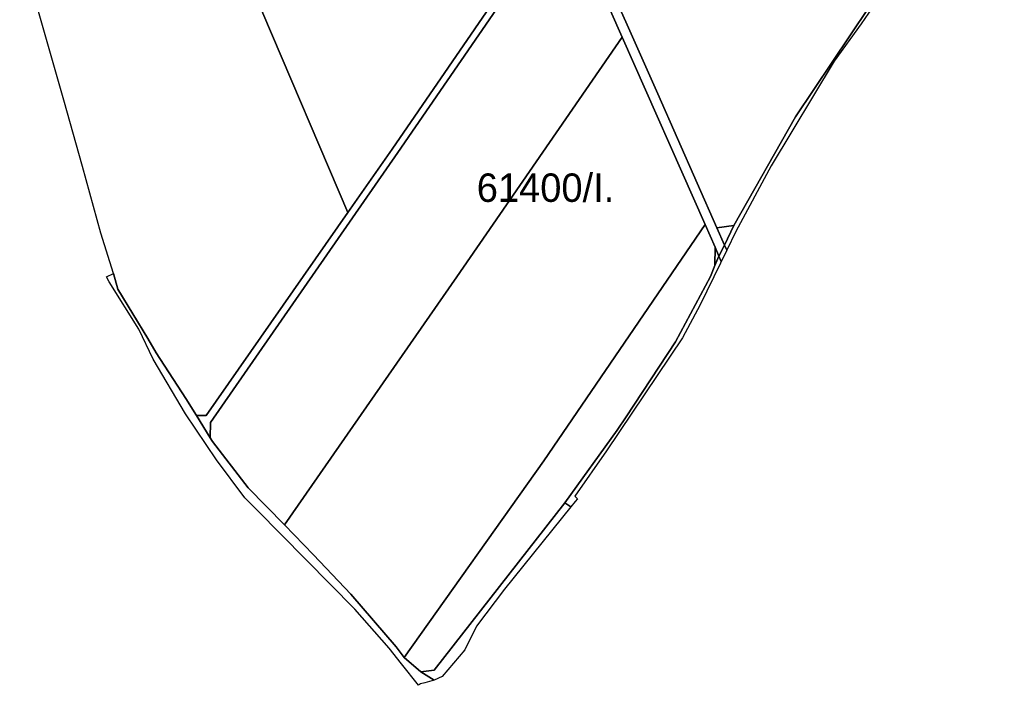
# Model space of a CAD drawing. Extents: x -522079 to -518792, y -1142400 to -1139961.
# Drawn here: x -521242 to -520720, y -1142400 to -1142050 of the extents above; entities that cross this region are included whole.
import ezdxf

# ---------------------------------------------------------------- set-up
doc = ezdxf.new("R2010")
doc.units = 0
for name, color, linetype in [('Hranice parcel', 7, 'Continuous'), ('Parcelní čísla', 7, 'Continuous'), ('Značky bodu BP', 7, 'Continuous')]:
    doc.layers.add(name, color=color, linetype=linetype)

msp = doc.modelspace()

# ---------------------------------------------------------------- linework, layer by layer
at = {"layer": 'Hranice parcel'}
for points in [[(-521009, -1141878.54), (-520995.39, -1141872.52), (-520997.93, -1141879.1), (-520967.25, -1141948.55), (-520939.85, -1142010.61), (-520905.36, -1142088.65), (-520874.16, -1142159.29), (-520870.13, -1142168.42), (-520873.11, -1142174.16), (-520875.14, -1142169.56), (-520880.4, -1142157.63), (-520924.06, -1142058.74), (-520951.97, -1141995.53), (-520958.2, -1141981.43), (-521002.46, -1141881.16)], [(-520870.13, -1142168.42), (-520868.95, -1142171.08), (-520869.86, -1142172.95), (-520871.84, -1142177.03), (-520873.11, -1142174.16)], [(-521030.26, -1142393.33), (-521023.14, -1142397.72), (-521028.09, -1142399.07), (-521030.42, -1142399.7), (-521031.51, -1142400.38), (-521040.41, -1142389.14), (-521046.98, -1142380.85), (-521064.97, -1142360.36), (-521116.76, -1142308), (-521123.05, -1142301.63), (-521137.94, -1142281.57), (-521154.24, -1142257.34), (-521171.39, -1142228.49), (-521178.89, -1142212.77), (-521194.57, -1142187.85), (-521195.91, -1142185.2), (-521192.34, -1142183.35), (-521189.97, -1142191.57), (-521174.19, -1142217.64), (-521169.79, -1142225.11), (-521154.1, -1142249.25), (-521148.58, -1142258.19), (-521141.26, -1142270.03), (-521140.11, -1142271.9), (-521121.26, -1142296.3), (-521102.18, -1142315.9), (-521086.87, -1142331.63), (-521067.07, -1142352.38), (-521043.28, -1142380.16), (-521039.1, -1142385.71)]]:
    msp.add_lwpolyline(points, close=True, dxfattribs=at)
at = {"layer": 'Parcelní čísla'}
for points in [[(-520997.93, -1141879.1), (-520995.39, -1141872.52), (-520888.63, -1141825.55), (-520837.29, -1141940.33), (-520792.44, -1142040.74), (-520794.02, -1142043.2), (-520832.63, -1142100.89), (-520865.14, -1142158.06), (-520874.16, -1142159.29), (-520905.36, -1142088.65), (-520939.85, -1142010.61), (-520967.25, -1141948.55)], [(-521068.69, -1142151.23), (-521113.51, -1142046.12), (-521154.29, -1141950.51), (-521103.17, -1141919.44), (-521009, -1141878.54), (-521002.46, -1141881.16), (-520958.2, -1141981.43), (-520958.22, -1141990.78), (-521045.32, -1142117.79)], [(-521235.48, -1141993.03), (-521178.81, -1141962.98), (-521154.29, -1141950.51), (-521113.51, -1142046.12), (-521068.69, -1142151.23), (-521143.48, -1142258.25), (-521148.58, -1142258.19), (-521154.1, -1142249.25), (-521169.79, -1142225.11), (-521174.19, -1142217.64), (-521189.97, -1142191.57), (-521192.34, -1142183.35), (-521198.94, -1142162.11), (-521208.63, -1142126.99), (-521218.49, -1142092.03), (-521226.84, -1142062.52), (-521233.47, -1142038.91), (-521241.65, -1142009.35)], [(-520865.14, -1142158.06), (-520832.63, -1142100.89), (-520794.02, -1142043.2), (-520792.44, -1142040.74), (-520762.92, -1142002.26), (-520751.6, -1141988.95), (-520732.26, -1141966.77), (-520721.33, -1141955.66), (-520719.53, -1141957.2), (-520728.5, -1141965.87), (-520748.85, -1141987.64), (-520778.35, -1142023.99), (-520792.36, -1142043.35), (-520798.04, -1142051.82), (-520812.28, -1142071.49), (-520845.48, -1142126.69), (-520864.2, -1142161.29), (-520868.95, -1142171.08), (-520870.13, -1142168.42)], [(-520951.97, -1141995.53), (-520956.88, -1141995.37), (-521042.42, -1142119.65), (-521141.2, -1142261.95), (-521141.26, -1142270.03), (-521148.58, -1142258.19), (-521143.48, -1142258.25), (-521068.69, -1142151.23), (-521045.32, -1142117.79), (-520958.22, -1141990.78), (-520958.2, -1141981.43)], [(-521011.25, -1142185.11), (-521102.18, -1142315.9), (-521121.26, -1142296.3), (-521140.11, -1142271.9), (-521141.26, -1142270.03), (-521141.2, -1142261.95), (-521042.42, -1142119.65), (-520956.88, -1141995.37), (-520951.97, -1141995.53), (-520924.06, -1142058.74)], [(-521039.1, -1142385.71), (-521043.28, -1142380.16), (-521067.07, -1142352.38), (-521086.87, -1142331.63), (-521102.18, -1142315.9), (-521011.25, -1142185.11), (-520924.06, -1142058.74), (-520880.4, -1142157.63), (-520965.43, -1142282.2)], [(-520875.14, -1142169.56), (-520875.23, -1142179.25), (-520877.61, -1142184.95), (-520896.04, -1142219.36), (-520921.99, -1142258.93), (-520926.78, -1142266.02), (-520954.32, -1142304.18), (-521023.14, -1142392.53), (-521030.26, -1142393.33), (-521039.1, -1142385.71), (-520965.43, -1142282.2), (-520880.4, -1142157.63)], [(-520865.14, -1142158.06), (-520870.13, -1142168.42), (-520874.16, -1142159.29)], [(-520875.14, -1142169.56), (-520873.11, -1142174.16), (-520875.23, -1142179.25)], [(-520873.11, -1142174.16), (-520871.84, -1142177.03), (-520872.25, -1142177.87), (-520882.99, -1142199.96), (-520892.25, -1142217.33), (-520932.3, -1142276.81), (-520949.04, -1142300.8), (-520947.69, -1142302.08), (-520948.83, -1142303.49), (-520951.1, -1142306.31), (-520954.32, -1142304.18), (-520926.78, -1142266.02), (-520921.99, -1142258.93), (-520896.04, -1142219.36), (-520877.61, -1142184.95), (-520875.23, -1142179.25)], [(-521030.26, -1142393.33), (-521023.14, -1142392.53), (-520954.32, -1142304.18), (-520951.1, -1142306.31), (-520986.1, -1142349.82), (-521000.81, -1142369.28), (-521007.1, -1142381.81), (-521018.9, -1142395.87), (-521023.14, -1142397.72)]]:
    msp.add_lwpolyline(points, close=True, dxfattribs=at)
at = {"layer": 'Značky bodu BP'}
msp.add_lwpolyline([(-520792.36, -1142043.35), (-520798.04, -1142051.82), (-520812.28, -1142071.49), (-520845.48, -1142126.69), (-520864.2, -1142161.29), (-520868.95, -1142171.08), (-520869.86, -1142172.95), (-520871.84, -1142177.03), (-520872.25, -1142177.87), (-520882.99, -1142199.96), (-520892.25, -1142217.33), (-520932.3, -1142276.81), (-520949.04, -1142300.8), (-520947.69, -1142302.08), (-520948.83, -1142303.49), (-520951.1, -1142306.31), (-520986.1, -1142349.82), (-521000.81, -1142369.28), (-521007.1, -1142381.81), (-521018.9, -1142395.87), (-521023.14, -1142397.72), (-521028.09, -1142399.07), (-521030.42, -1142399.7), (-521031.51, -1142400.38), (-521040.41, -1142389.14), (-521046.98, -1142380.85), (-521064.97, -1142360.36), (-521116.76, -1142308), (-521123.05, -1142301.63), (-521137.94, -1142281.57), (-521154.24, -1142257.34), (-521171.39, -1142228.49), (-521178.89, -1142212.77), (-521194.57, -1142187.85), (-521195.91, -1142185.2), (-521192.34, -1142183.35), (-521198.94, -1142162.11), (-521208.63, -1142126.99), (-521218.49, -1142092.03), (-521226.84, -1142062.52), (-521233.47, -1142038.91)], dxfattribs=at)

# ---------------------------------------------------------------- texts
msp.add_text('61400/I.', height=15, rotation=0, dxfattribs=at).set_placement((-521000.75, -1142145.64))

doc.saveas('drawing.dxf')
